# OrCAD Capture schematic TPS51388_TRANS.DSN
size Custom; title: TPS51388, 5.5-V to 24-V input, 12-A Synchronous; rev: 1.0; note: Datasheet: SLUSFU4     EVM: SLUUD53; note: Synchronous Step Down Converter; note: Step-Down Voltage Regulator
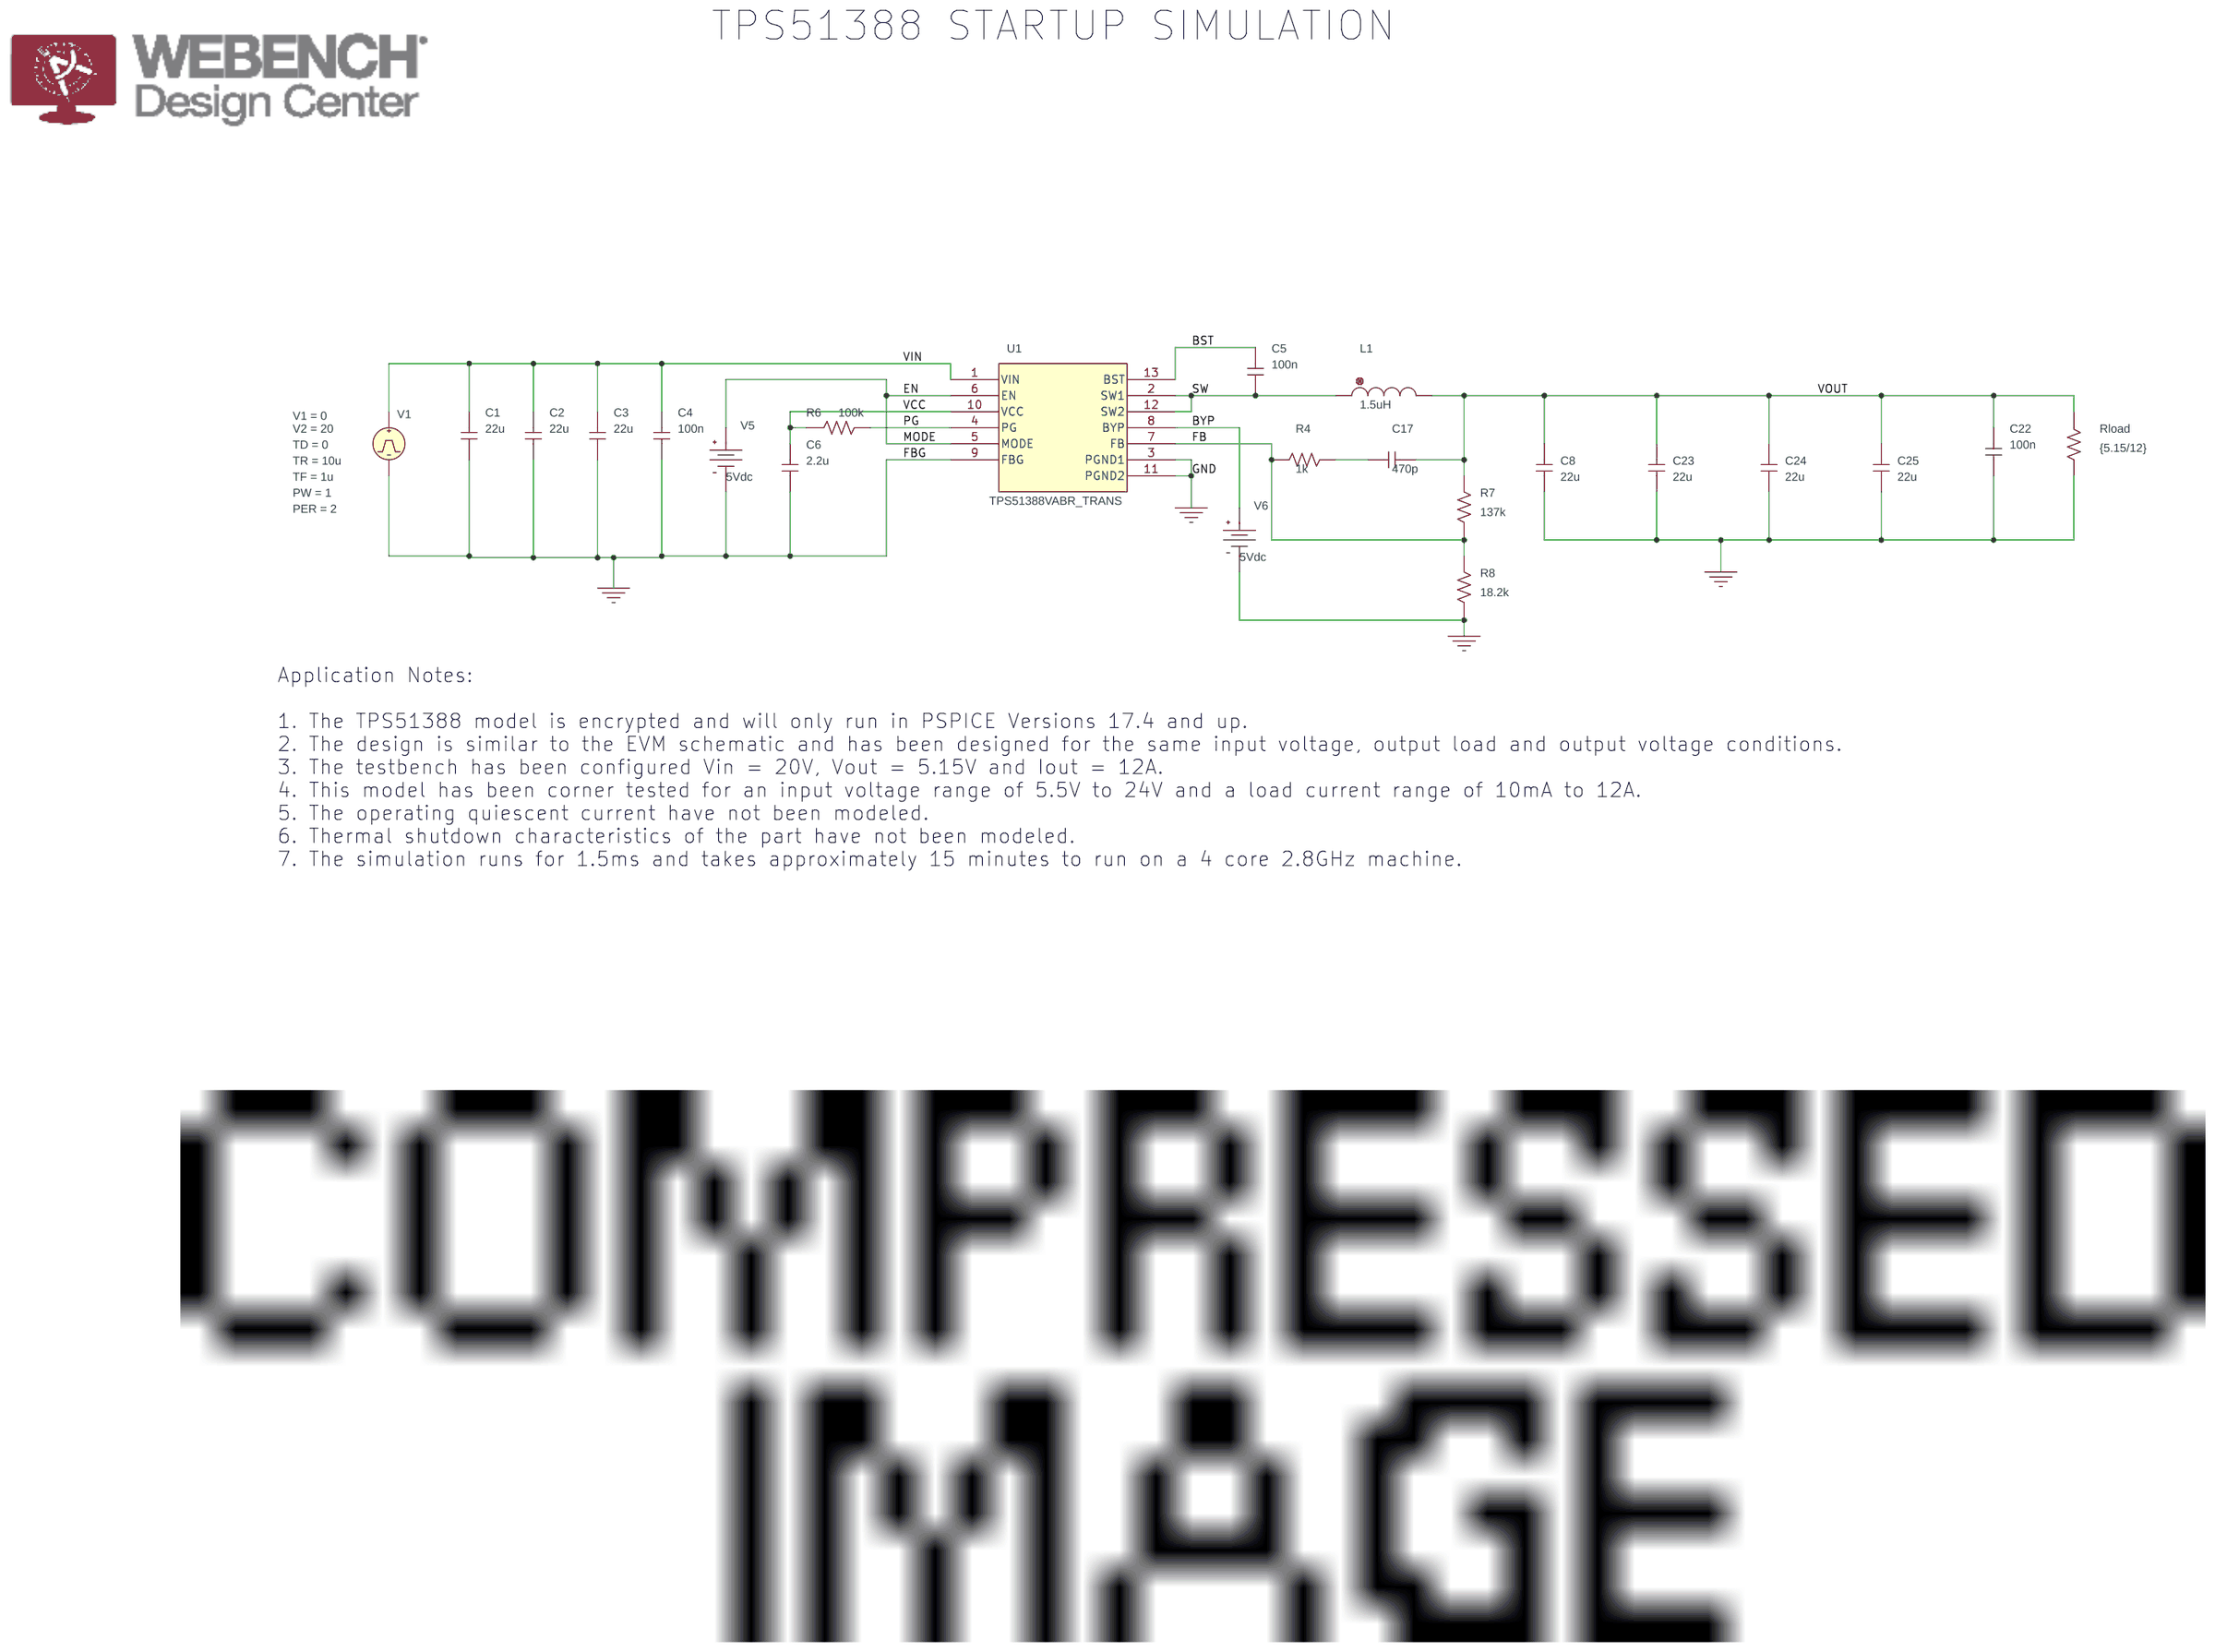
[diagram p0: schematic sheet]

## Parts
C1  22u  [RAD/CK05]
C2  22u  [RAD/CK05]
C3  22u  [RAD/CK05]
C4  100n  [RAD/CK05]
C5  100n  [RAD/CK05]
C6  2.2u  [RAD/CK05]
C8  22u  [cap196]
C17  470p  [cap196]
C22  100n  [RAD/CK05]
C23  22u  [cap196]
C24  22u  [cap196]
C25  22u  [cap196]
L1  1.5uH  [DISC350x175LS200x100034]
R4  1k  [AXRC05]
R6  100k  [AX/RC05]
R7  137k  [AXRC05]
R8  18.2k  [AXRC05]
Rload  {5.15/12}  [AX/RC05]
U1  TPS51388VABR_TRANS
V1  VPULSE
V5  VDC
V6  VDC

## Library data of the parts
C1-C6 C8 C17 C22-C25 = C
L1 = L
R4 R6-R8 Rload = R
U1 = TPS51388VABR_TRANS
V1 = VPULSE: PER: 2; PW: 1; TD: 0; TF: 1u; TR: 10u; V1: 0; V2: 20
V5 V6 = VDC: DC: 5Vdc

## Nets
VCC: C6.1 R6.1 U1.10(VCC)
VIN: C1.1 C2.1 C3.1 C4.1 U1.1(VIN) V1.1(+)
0: C1.2 C2.2 C3.2 C4.2 C6.2 C8.1 C22.2 C23.1 C24.1 C25.1 R8.1 Rload.2 U1.3(PGND1) U1.9(FBG) U1.11(PGND2) V1.2(-) V5.1(-) V6.1(-)
BST: C5.1 U1.13(BST)
BYP: U1.8(BYP) V6.0(+)
EN: U1.5(MODE) U1.6(EN) V5.0(+)
FB: R4.1 R7.1 R8.2 U1.7(FB)
PG: R6.2 U1.4(PG)
SW: C5.2 L1.1 U1.2(SW1) U1.12(SW2)
VOUT: C8.2 C17.2 C22.1 C23.2 C24.2 C25.2 L1.2 R7.2 Rload.1
N23363: C17.1 R4.2

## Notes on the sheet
- TPS51388 STARTUP SIMULATION
- Application Notes:
  1. The TPS51388 model is encrypted and will only run in PSPICE Versions 17.4 and up.
  2. The design is similar to the EVM schematic and has been designed for the same input voltage, output load and output voltage conditions.
  3. The testbench has been configured Vin = 20V, Vout = 5.15V and Iout = 12A.
  4. This model has been corner tested for an input voltage range of 5.5V to 24V and a load current range of 10mA to 12A.
  5. The operating quiescent current have not been modeled.
  6. Thermal shutdown characteristics of the part have not been modeled.
  7. The simulation runs for 1.5ms and takes approximately 15 minutes to run on a 4 core 2.8GHz machine.
